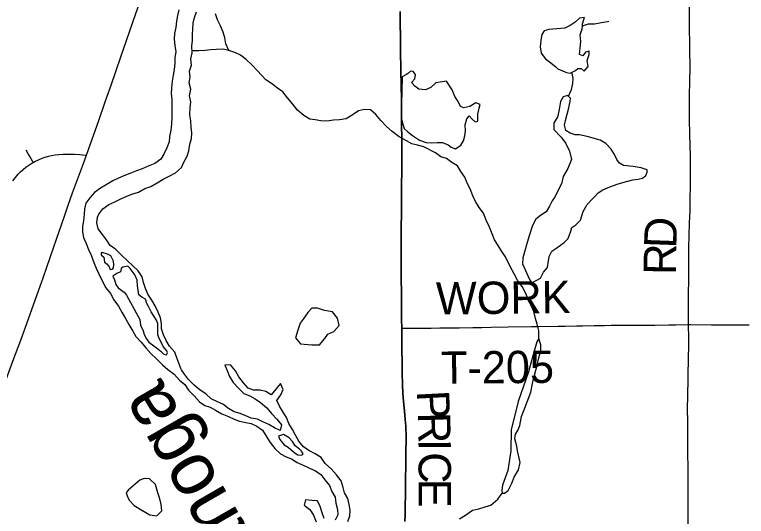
# Model space of a CAD drawing. Extents: x 0 to 34, y 0 to 22.
# Drawn here: x 4.358 to 5.643, y 18.429 to 19.311 of the extents above; entities that cross this region are included whole.
import ezdxf

# ---------------------------------------------------------------- set-up
doc = ezdxf.new("R2010")
doc.units = 0
for name, color, linetype in [('GM_X_City_Street', 7, 'Continuous'), ('GM_X_Corporation', 7, 'Continuous'), ('GM_X_County_Road', 7, 'Continuous'), ('GM_X_County_Road_Text', 7, 'Continuous'), ('GM_X_Major_River', 7, 'Continuous'), ('GM_X_Major_River_Text', 7, 'Continuous'), ('GM_X_Minor_Lake', 7, 'Continuous'), ('GM_X_Minor_River', 7, 'Continuous'), ('GM_X_Township_Road', 7, 'Continuous'), ('GM_X_Township_Road_Text', 7, 'Continuous')]:
    doc.layers.add(name, color=color, linetype=linetype)

msp = doc.modelspace()

# ---------------------------------------------------------------- linework, layer by layer
at = {"layer": 'GM_X_City_Street'}
for points in [[(4.3544, 19.0187), (4.3594, 19.0249), (4.3642, 19.0306), (4.3683, 19.0347), (4.3726, 19.0387), (4.3774, 19.0426), (4.3824, 19.0462), (4.3878, 19.0497), (4.3904, 19.051), (4.393, 19.0525), (4.3995, 19.0556), (4.4059, 19.0585), (4.4115, 19.0604), (4.417, 19.0621), (4.4225, 19.0633), (4.4291, 19.0645), (4.4355, 19.0652), (4.4432, 19.0658), (4.4525, 19.0658), (4.4626, 19.0657), (4.4723, 19.0651), (4.4818, 19.0641), (4.4839, 19.0639)], [(4.3904, 19.051), (4.3897, 19.0522), (4.3838, 19.0626), (4.381, 19.0674), (4.378, 19.0725)]]:
    msp.add_lwpolyline(points, dxfattribs=at)
at = {"layer": 'GM_X_Corporation'}
for points in [[(5.0433, 18.4204), (5.0435, 18.4306), (5.0437, 18.4402), (5.0439, 18.4515), (5.0441, 18.4627), (5.0443, 18.474), (5.0444, 18.4842), (5.0446, 18.4992), (5.0447, 18.5132), (5.0451, 18.5363), (5.0452, 18.5462), (5.0455, 18.5599), (5.0455, 18.5667), (5.0455, 18.5743), (5.0452, 18.582), (5.0449, 18.5875), (5.044, 18.5992), (5.0426, 18.6137), (5.0403, 18.6381), (5.0398, 18.6453), (5.0394, 18.6506), (5.0391, 18.6562), (5.0388, 18.6671), (5.0386, 18.6755), (5.0384, 18.6871), (5.0382, 18.7016), (5.0379, 18.721), (5.0377, 18.736), (5.0376, 18.7601), (5.0374, 18.7747), (5.0372, 18.7908), (5.0372, 18.8147), (5.0372, 18.8259), (5.037, 18.8431), (5.037, 18.8569), (5.0369, 18.8664), (5.0368, 18.8922), (5.0367, 18.9116), (5.0369, 18.9377), (5.0371, 18.9607), (5.0372, 18.9701), (5.0373, 18.9876), (5.0374, 19.0028), (5.0375, 19.0127), (5.0377, 19.0343), (5.038, 19.0561), (5.0379, 19.0696), (5.0378, 19.0934), (5.0375, 19.1174), (5.0374, 19.1254), (5.0373, 19.145), (5.0372, 19.1591), (5.0371, 19.1704), (5.037, 19.1778), (5.0367, 19.1888), (5.0362, 19.211), (5.036, 19.2246), (5.0358, 19.237), (5.0355, 19.2584), (5.0353, 19.2747), (5.035, 19.2928), (5.0349, 19.3162)], [(5.0433, 18.4204), (5.0435, 18.4306), (5.0437, 18.4402), (5.0439, 18.4515), (5.0441, 18.4627), (5.0443, 18.474), (5.0444, 18.4842), (5.0446, 18.4992), (5.0447, 18.5132), (5.0451, 18.5363), (5.0452, 18.5462), (5.0455, 18.5599), (5.0455, 18.5667), (5.0455, 18.5743), (5.0452, 18.582), (5.0449, 18.5875), (5.044, 18.5992), (5.0426, 18.6137), (5.0403, 18.6381), (5.0398, 18.6453), (5.0394, 18.6506), (5.0391, 18.6562), (5.0388, 18.6671), (5.0386, 18.6755), (5.0384, 18.6871), (5.0382, 18.7016), (5.0379, 18.721), (5.0377, 18.736), (5.0376, 18.7601), (5.0374, 18.7747), (5.0372, 18.7908), (5.0372, 18.8147), (5.0372, 18.8259), (5.037, 18.8431), (5.037, 18.8569), (5.0369, 18.8664), (5.0368, 18.8922), (5.0367, 18.9116), (5.0369, 18.9377), (5.0371, 18.9607), (5.0372, 18.9701), (5.0373, 18.9876), (5.0374, 19.0028), (5.0375, 19.0127), (5.0377, 19.0343), (5.038, 19.0561), (5.0379, 19.0696), (5.0378, 19.0934), (5.0375, 19.1174), (5.0374, 19.1254), (5.0373, 19.145), (5.0372, 19.1591), (5.0371, 19.1704), (5.037, 19.1778), (5.0367, 19.1888), (5.0362, 19.211), (5.036, 19.2246), (5.0358, 19.237), (5.0355, 19.2584), (5.0353, 19.2747), (5.035, 19.2928), (5.0349, 19.3162)], [(5.0349, 19.3162), (5.035, 19.2928), (5.0353, 19.2747), (5.0355, 19.2584), (5.0358, 19.237), (5.036, 19.2246), (5.0362, 19.211), (5.0367, 19.1888), (5.037, 19.1778), (5.0371, 19.1704), (5.0372, 19.1591), (5.0373, 19.145), (5.0374, 19.1254), (5.0375, 19.1174), (5.0378, 19.0934), (5.0379, 19.0696), (5.038, 19.0561), (5.0377, 19.0343), (5.0375, 19.0127), (5.0374, 19.0028), (5.0373, 18.9876), (5.0372, 18.9701), (5.0371, 18.9607), (5.0369, 18.9377), (5.0367, 18.9116), (5.0368, 18.8922), (5.0369, 18.8664), (5.037, 18.8569), (5.037, 18.8431), (5.0372, 18.8259), (5.0372, 18.8147), (5.0372, 18.7908), (5.0374, 18.7747), (5.0376, 18.7601), (5.0377, 18.736), (5.0379, 18.721), (5.0382, 18.7016), (5.0384, 18.6871), (5.0386, 18.6755), (5.0388, 18.6671), (5.0391, 18.6562), (5.0394, 18.6506), (5.0398, 18.6453), (5.0403, 18.6381), (5.0426, 18.6137), (5.044, 18.5992), (5.0449, 18.5875), (5.0452, 18.582), (5.0455, 18.5743), (5.0455, 18.5667), (5.0455, 18.5599), (5.0452, 18.5462), (5.0451, 18.5363), (5.0447, 18.5132), (5.0446, 18.4992), (5.0444, 18.4842), (5.0443, 18.474), (5.0441, 18.4627), (5.0439, 18.4515), (5.0437, 18.4402), (5.0435, 18.4306), (5.0433, 18.4204)]]:
    msp.add_lwpolyline(points, dxfattribs=at)
at = {"layer": 'GM_X_County_Road'}
for points in [[(4.4839, 19.0639), (4.4909, 19.0836), (4.5051, 19.1233), (4.5169, 19.1574), (4.527, 19.1868), (4.5441, 19.2367), (4.5702, 19.3113), (4.5896, 19.367), (4.6075, 19.4161), (4.6147, 19.4353), (4.6273, 19.4684), (4.6389, 19.498), (4.6405, 19.5022), (4.6422, 19.506), (4.6444, 19.5103), (4.6464, 19.5143), (4.6507, 19.5222), (4.6645, 19.5462), (4.6819, 19.5749), (4.704, 19.6102), (4.7229, 19.6416), (4.7349, 19.6613), (4.7525, 19.6876), (4.7582, 19.6961)], [(5.5416, 18.766), (5.5416, 18.7696), (5.5416, 18.7796), (5.5417, 18.8106), (5.542, 18.8535), (5.5419, 18.8777), (5.5419, 18.8882), (5.5422, 18.9006), (5.5427, 18.9225), (5.5435, 18.9448), (5.5442, 18.9652), (5.5443, 18.9701), (5.5445, 18.9794), (5.545, 19.0167), (5.5451, 19.0366), (5.5451, 19.0631), (5.5445, 19.0804), (5.5437, 19.1009), (5.5435, 19.1264), (5.5433, 19.1469), (5.5435, 19.1674), (5.544, 19.1947), (5.5443, 19.2171), (5.544, 19.2494), (5.5434, 19.2978), (5.5429, 19.3687)], [(4.3111, 18.581), (4.3127, 18.5856), (4.3213, 18.6094), (4.3384, 18.6567), (4.3547, 18.7017), (4.3685, 18.7389), (4.3821, 18.7762), (4.4003, 18.8271), (4.4077, 18.8483), (4.421, 18.8857), (4.4315, 18.9162), (4.4455, 18.9567), (4.4518, 18.9761), (4.4596, 18.9976), (4.4769, 19.0444), (4.4839, 19.0639)], [(5.5406, 18.402), (5.5406, 18.4299), (5.541, 18.4628), (5.5408, 18.4795), (5.5408, 18.5), (5.5408, 18.518), (5.5405, 18.5367), (5.5403, 18.5572), (5.5402, 18.5833), (5.54, 18.5988), (5.5398, 18.6144), (5.5402, 18.6442), (5.5405, 18.6504), (5.5408, 18.6616), (5.5411, 18.6845), (5.5412, 18.6982), (5.5419, 18.738), (5.5418, 18.7435), (5.5416, 18.7647), (5.5416, 18.766)]]:
    msp.add_lwpolyline(points, dxfattribs=at)
at = {"layer": 'GM_X_Major_River'}
for p, q in [((4.5142, 18.8844), (4.5154, 18.8757)), ((4.5576, 18.8112), (4.5779, 18.7749)), ((4.8313, 18.5546), (4.8381, 18.5505))]:
    msp.add_line(p, q, dxfattribs=at)
for points in [[(4.646, 19.3193), (4.6438, 19.3095), (4.642, 19.2992), (4.6406, 19.2882), (4.6387, 19.2776), (4.6381, 19.2677), (4.6393, 19.2567), (4.6409, 19.2457), (4.6394, 19.2358), (4.6391, 19.2256), (4.6381, 19.2142), (4.6363, 19.2047), (4.6345, 19.1941), (4.6334, 19.1823), (4.6327, 19.1721), (4.6336, 19.1618), (4.6338, 19.1307), (4.6335, 19.1182), (4.6321, 19.108), (4.6299, 19.0966), (4.6292, 19.0871), (4.6248, 19.0768), (4.6203, 19.0669), (4.6143, 19.057), (4.6038, 19.0493), (4.5925, 19.0447), (4.5819, 19.0401), (4.5717, 19.0362), (4.56, 19.0319), (4.5498, 19.0273), (4.54, 19.0234), (4.5302, 19.0188), (4.5186, 19.0119), (4.5084, 19.0057), (4.4982, 18.9984), (4.49, 18.9889), (4.4825, 18.9794), (4.4807, 18.9695), (4.4796, 18.96), (4.4789, 18.9482), (4.4771, 18.9383), (4.4768, 18.9289), (4.4788, 18.919), (4.4834, 18.9084), (4.4873, 18.8982), (4.4919, 18.888), (4.4969, 18.8752), (4.5008, 18.8653), (4.5054, 18.8555), (4.5112, 18.843), (4.5181, 18.8306), (4.5261, 18.8208), (4.5318, 18.8098), (4.5399, 18.7985), (4.5464, 18.7868), (4.5522, 18.777), (4.5583, 18.7664), (4.5656, 18.7547), (4.5709, 18.7449), (4.5801, 18.7351), (4.5881, 18.7253), (4.5969, 18.7155), (4.6072, 18.7057), (4.6175, 18.6952), (4.627, 18.6873), (4.6377, 18.679), (4.6472, 18.6685), (4.6567, 18.661), (4.6633, 18.6508), (4.6728, 18.641), (4.6823, 18.6304), (4.6919, 18.6237), (4.7013, 18.6207), (4.7108, 18.6159), (4.7219, 18.6091), (4.7336, 18.6047), (4.7435, 18.5998), (4.753, 18.5961), (4.7636, 18.5939), (4.7735, 18.5921), (4.783, 18.5872), (4.7929, 18.5805), (4.8005, 18.5684), (4.8067, 18.5586), (4.8147, 18.548), (4.825, 18.5386), (4.8348, 18.5338), (4.8443, 18.53), (4.8542, 18.5237), (4.8645, 18.5192), (4.8744, 18.514), (4.8861, 18.5091), (4.8956, 18.5028)], [(4.5031, 18.9548), (4.5057, 18.9601), (4.5128, 18.9697), (4.5233, 18.9774), (4.5339, 18.9817), (4.544, 18.9871), (4.5546, 18.9918), (4.5655, 18.9957), (4.5753, 18.9989), (4.5862, 19.0051), (4.5972, 19.009), (4.6081, 19.0152), (4.6186, 19.0214), (4.6292, 19.0272), (4.6405, 19.0331), (4.651, 19.0423), (4.655, 19.0518), (4.6606, 19.0622), (4.6635, 19.0717), (4.6653, 19.0831), (4.6686, 19.093), (4.6688, 19.1029), (4.668, 19.1128), (4.6671, 19.1234), (4.6655, 19.1351), (4.6661, 19.1473), (4.6671, 19.1576), (4.6651, 19.1682), (4.6672, 19.1796), (4.6644, 19.1913), (4.6662, 19.2012), (4.665, 19.2118), (4.6683, 19.2218), (4.667, 19.2335), (4.6695, 19.2438), (4.6687, 19.2552), (4.6701, 19.2655), (4.6699, 19.2757), (4.6706, 19.2852), (4.6716, 19.2962), (4.6738, 19.3061), (4.6771, 19.316)], [(4.6496, 18.6891), (4.6428, 18.7079), (4.6389, 18.7177), (4.6297, 18.7283), (4.624, 18.7381), (4.6194, 18.7483), (4.6159, 18.7585), (4.6158, 18.768), (4.6138, 18.7778), (4.6096, 18.7877), (4.6046, 18.799), (4.5985, 18.8088), (4.5916, 18.8198), (4.5877, 18.8296), (4.5842, 18.8398), (4.5815, 18.85), (4.575, 18.8606), (4.5654, 18.8696), (4.5555, 18.8787), (4.546, 18.8877), (4.5357, 18.8982), (4.5254, 18.905), (4.5193, 18.9148), (4.512, 18.9246), (4.5044, 18.9344), (4.502, 18.945), (4.5031, 18.9548)], [(4.5154, 18.8757), (4.52, 18.8723), (4.5235, 18.8678), (4.5258, 18.8629), (4.5295, 18.8633), (4.5314, 18.8656), (4.5321, 18.8713), (4.5313, 18.8773), (4.5267, 18.8868), (4.5206, 18.8898), (4.513, 18.8924), (4.51, 18.8919), (4.51, 18.8889), (4.5142, 18.8844)], [(4.5779, 18.7749), (4.5791, 18.765), (4.5837, 18.7548), (4.5853, 18.7484), (4.5891, 18.7412), (4.5934, 18.7352), (4.6021, 18.7288), (4.6093, 18.7236), (4.6151, 18.7187), (4.62, 18.7138), (4.6242, 18.7131), (4.6264, 18.7165), (4.6249, 18.7199), (4.6184, 18.7274), (4.6157, 18.7342), (4.6122, 18.7407), (4.6095, 18.7482), (4.6095, 18.7569), (4.609, 18.7679), (4.6067, 18.774), (4.6017, 18.7819), (4.5975, 18.7883), (4.5925, 18.7989), (4.5902, 18.8034), (4.5875, 18.8106), (4.581, 18.8144), (4.5757, 18.8185), (4.5737, 18.834), (4.5732, 18.8443), (4.5701, 18.8511), (4.5674, 18.8552), (4.5606, 18.8647), (4.5567, 18.8688), (4.5477, 18.8672), (4.545, 18.8645), (4.5436, 18.8585), (4.5372, 18.8561), (4.5304, 18.8511), (4.5331, 18.8447), (4.5354, 18.8364), (4.5396, 18.8304), (4.5499, 18.8229), (4.5541, 18.818), (4.5576, 18.8112)], [(4.9429, 18.42), (4.9466, 18.4299), (4.9472, 18.4398), (4.9452, 18.45), (4.9428, 18.4602), (4.9374, 18.4701), (4.935, 18.4799), (4.9315, 18.4913), (4.9234, 18.5022), (4.9142, 18.5119), (4.9035, 18.5217), (4.8962, 18.5326), (4.8859, 18.5386), (4.8745, 18.5449), (4.8649, 18.5512), (4.8569, 18.561), (4.8511, 18.5716), (4.8457, 18.5818), (4.8391, 18.5923), (4.8352, 18.6025), (4.8294, 18.6123), (4.8229, 18.6225), (4.8182, 18.6327), (4.8253, 18.6423), (4.8297, 18.6522), (4.8247, 18.6624), (4.8165, 18.6524), (4.8086, 18.6425), (4.7987, 18.6484), (4.7892, 18.6506), (4.7775, 18.6508), (4.768, 18.6541), (4.7599, 18.6639), (4.7518, 18.6745), (4.7457, 18.6846), (4.7368, 18.6952), (4.727, 18.695), (4.7313, 18.6852), (4.7352, 18.6746), (4.7414, 18.6641), (4.7509, 18.6543), (4.7605, 18.6449), (4.7708, 18.6409), (4.7803, 18.6353), (4.7898, 18.6293), (4.8006, 18.6196), (4.809, 18.6098), (4.8182, 18.6), (4.8263, 18.5899), (4.8241, 18.58), (4.8142, 18.5844), (4.8043, 18.5904), (4.7936, 18.5952), (4.7841, 18.5996), (4.7735, 18.6014), (4.7636, 18.6055), (4.7541, 18.6095), (4.7435, 18.6125), (4.7332, 18.6184), (4.7236, 18.6259), (4.7141, 18.6303), (4.7031, 18.6355), (4.6935, 18.6441), (4.6839, 18.6505), (4.6732, 18.6595), (4.6633, 18.6696), (4.6561, 18.6789), (4.651, 18.6866), (4.6496, 18.6891)], [(4.8381, 18.5505), (4.8431, 18.5467), (4.8465, 18.5433), (4.8503, 18.54), (4.8553, 18.5373), (4.8621, 18.5363), (4.8643, 18.5389), (4.8616, 18.5438), (4.8582, 18.5468), (4.8506, 18.5532), (4.846, 18.5604), (4.8399, 18.5668), (4.83, 18.5728), (4.8213, 18.5701), (4.8236, 18.564), (4.8313, 18.5546)], [(4.8956, 18.5028), (4.9029, 18.493), (4.9106, 18.4831), (4.9152, 18.4729), (4.9206, 18.4624), (4.9221, 18.4521), (4.9249, 18.4412), (4.9253, 18.4317), (4.9209, 18.4222)], [(4.9012, 18.4254), (4.8977, 18.4353), (4.8946, 18.4462), (4.8899, 18.4564), (4.8797, 18.4567), (4.8687, 18.4582), (4.8665, 18.4487), (4.8764, 18.4408), (4.883, 18.431), (4.8872, 18.4192)]]:
    msp.add_lwpolyline(points, dxfattribs=at)
at = {"layer": 'GM_X_Minor_Lake'}
for p, q in [((5.3244, 19.287), (5.2961, 19.2849)), ((5.0382, 19.2014), (5.0365, 19.1293)), ((5.3182, 19.0137), (5.3059, 18.9892)), ((4.873, 18.7874), (4.8644, 18.7756)), ((5.2602, 18.6831), (5.2425, 18.631)), ((4.5774, 18.4923), (4.5571, 18.4747))]:
    msp.add_line(p, q, dxfattribs=at)
for points in [[(5.2961, 19.2849), (5.2881, 19.2822), (5.2837, 19.2757), (5.2822, 19.2659), (5.2808, 19.2541), (5.2828, 19.2431), (5.2904, 19.2333), (5.2973, 19.2277), (5.3083, 19.2194), (5.3121, 19.2156), (5.3201, 19.2119), (5.3269, 19.2093), (5.3338, 19.2082), (5.3432, 19.2125), (5.3473, 19.2163), (5.353, 19.216), (5.3583, 19.2118), (5.3651, 19.2195), (5.3635, 19.2305), (5.3668, 19.2411), (5.3668, 19.2464), (5.3603, 19.2448), (5.3558, 19.2387), (5.3502, 19.241), (5.3512, 19.2524), (5.3523, 19.2634), (5.3514, 19.2755), (5.3547, 19.2861), (5.3551, 19.2903), (5.355, 19.2949), (5.3587, 19.3059), (5.35, 19.3047), (5.3425, 19.2978), (5.3335, 19.2917), (5.3244, 19.287)], [(5.0365, 19.1293), (5.0396, 19.1183), (5.042, 19.1108), (5.0484, 19.1048), (5.0568, 19.0984), (5.069, 19.0901), (5.0804, 19.0864), (5.0906, 19.0854), (5.1, 19.0862), (5.1095, 19.0859), (5.1194, 19.0818), (5.1247, 19.0777), (5.1323, 19.0751), (5.1413, 19.0816), (5.1462, 19.0892), (5.1484, 19.0976), (5.1498, 19.1067), (5.1494, 19.1173), (5.152, 19.1279), (5.1561, 19.1333), (5.161, 19.128), (5.1668, 19.1224), (5.1713, 19.1239), (5.1716, 19.1357), (5.1738, 19.1467), (5.1756, 19.1531), (5.1676, 19.1561), (5.1575, 19.1492), (5.1469, 19.1469), (5.1408, 19.1495), (5.137, 19.1582), (5.1312, 19.1672), (5.1262, 19.1789), (5.1166, 19.1937), (5.0977, 19.1909), (5.0891, 19.1828), (5.0797, 19.1786), (5.0675, 19.18), (5.0607, 19.1849), (5.0561, 19.1902), (5.0557, 19.1924), (5.0606, 19.1982), (5.0617, 19.2054), (5.0575, 19.211), (5.0533, 19.2114), (5.0495, 19.2083), (5.0458, 19.2056), (5.0382, 19.2014)], [(5.3059, 18.9892), (5.3022, 18.9838), (5.297, 18.9743), (5.2914, 18.9644), (5.2812, 18.9579), (5.2733, 18.9513), (5.2677, 18.9403), (5.2618, 18.9221), (5.257, 18.9061), (5.254, 18.8958), (5.2503, 18.8833), (5.2497, 18.8727), (5.2551, 18.8613), (5.262, 18.8454), (5.2662, 18.8394), (5.2813, 18.8475), (5.2869, 18.8581), (5.294, 18.8665), (5.2958, 18.8783), (5.2965, 18.8859), (5.3014, 18.895), (5.3104, 18.9012), (5.3232, 18.9104), (5.3299, 18.9176), (5.334, 18.9287), (5.3366, 18.937), (5.3434, 18.9413), (5.352, 18.9497), (5.3564, 18.9649), (5.3632, 18.9771), (5.3729, 18.9874), (5.3767, 18.9912), (5.3827, 18.9977), (5.391, 19.0031), (5.4034, 19.0081), (5.4181, 19.0132), (5.4325, 19.0174), (5.4438, 19.0206), (5.4529, 19.0214), (5.4605, 19.0233), (5.4665, 19.0283), (5.4691, 19.034), (5.4687, 19.0382), (5.4584, 19.0415), (5.4444, 19.0437), (5.4274, 19.0458), (5.4205, 19.0496), (5.4155, 19.056), (5.4113, 19.0651), (5.4056, 19.0745), (5.3964, 19.0843), (5.3861, 19.0903), (5.3634, 19.0969), (5.3497, 19.0995), (5.3422, 19.0994), (5.3334, 19.1024), (5.3258, 19.1073), (5.3239, 19.1164), (5.3253, 19.1251), (5.3286, 19.1357), (5.3308, 19.1445), (5.3338, 19.1585), (5.3341, 19.1638), (5.3291, 19.1687), (5.3212, 19.1664), (5.3167, 19.1584), (5.3142, 19.144), (5.3113, 19.1307), (5.3049, 19.1208), (5.3046, 19.109), (5.3176, 19.0954), (5.326, 19.0841), (5.3322, 19.0709), (5.3357, 19.0561), (5.3294, 19.0405), (5.3212, 19.0264), (5.3182, 19.0137)], [(4.8644, 18.7756), (4.8595, 18.7684), (4.8551, 18.7562), (4.851, 18.7425), (4.8598, 18.732), (4.8795, 18.7302), (4.8935, 18.7303), (4.9029, 18.7414), (4.9081, 18.749), (4.9183, 18.754), (4.9277, 18.7647), (4.9249, 18.7772), (4.9161, 18.7885), (4.9021, 18.7907), (4.8896, 18.7948), (4.8798, 18.7951), (4.873, 18.7874)], [(5.2425, 18.631), (5.23, 18.5808), (5.2295, 18.5444), (5.2241, 18.5095), (5.2145, 18.4836), (5.2134, 18.4752), (5.2142, 18.4699), (5.218, 18.47), (5.2247, 18.4746), (5.2311, 18.4871), (5.2352, 18.4978), (5.2426, 18.5107), (5.2456, 18.5237), (5.2412, 18.5441), (5.24, 18.5524), (5.2381, 18.5585), (5.2365, 18.5653), (5.2376, 18.5733), (5.2417, 18.5801), (5.2454, 18.5889), (5.2483, 18.6045), (5.2532, 18.6178), (5.258, 18.6303), (5.2643, 18.6471), (5.2676, 18.6627), (5.2709, 18.6771), (5.2756, 18.695), (5.2786, 18.7079), (5.2823, 18.7204), (5.2822, 18.7307), (5.2787, 18.7416), (5.2753, 18.7355), (5.2702, 18.7196), (5.2654, 18.7021), (5.2602, 18.6831)], [(4.5571, 18.4747), (4.5538, 18.4705), (4.5553, 18.4648), (4.5592, 18.4573), (4.5676, 18.4482), (4.5809, 18.44), (4.5953, 18.4314), (4.6078, 18.43), (4.6161, 18.4384), (4.6149, 18.4498), (4.6129, 18.4596), (4.609, 18.4702), (4.6051, 18.4849), (4.5945, 18.4951), (4.5854, 18.4954), (4.5774, 18.4923)]]:
    msp.add_lwpolyline(points, dxfattribs=at)
at = {"layer": 'GM_X_Minor_River'}
for points in [[(4.734, 19.2476), (4.729, 19.2597), (4.727, 19.2699), (4.7243, 19.2801), (4.7192, 19.2911), (4.7139, 19.302), (4.7104, 19.3123)], [(5.3551, 19.2915), (5.366, 19.2946), (5.3766, 19.2947), (5.3887, 19.297), (5.3989, 19.299), (5.4016, 19.2994)], [(5.2787, 18.7416), (5.2786, 18.7549), (5.2758, 18.7666), (5.2727, 18.7765), (5.2696, 18.789), (5.2642, 18.8007), (5.2596, 18.8109), (5.2554, 18.8219), (5.2492, 18.8332), (5.2416, 18.843), (5.235, 18.8555), (5.2289, 18.8668), (5.2201, 18.8849), (5.2136, 18.8948), (5.207, 18.9053), (5.2005, 18.9151), (5.1967, 18.9257), (5.1917, 18.9371), (5.1863, 18.9495), (5.1816, 18.962), (5.174, 18.9718), (5.1675, 18.9824), (5.1628, 18.9922), (5.1582, 19.0047), (5.1528, 19.0149), (5.1486, 19.0251), (5.1417, 19.0349), (5.1356, 19.0451), (5.1257, 19.0507), (5.1162, 19.0582), (5.1063, 19.0612), (5.0968, 19.068), (5.0763, 19.0784), (5.0656, 19.0814), (5.0554, 19.0839), (5.0459, 19.0888), (5.0334, 19.0963), (5.0208, 19.1053), (5.0109, 19.1143), (5.001, 19.1249), (4.9922, 19.1354), (4.9827, 19.1433), (4.9721, 19.1444), (4.9615, 19.142), (4.9506, 19.1343), (4.94, 19.1278), (4.9283, 19.1258), (4.9177, 19.1254), (4.9064, 19.1238), (4.8958, 19.1241), (4.8859, 19.1259), (4.8761, 19.1269), (4.8658, 19.1337), (4.8544, 19.1427), (4.8467, 19.1533), (4.8372, 19.1646), (4.8291, 19.1751), (4.8196, 19.1815), (4.809, 19.1898), (4.7987, 19.1965), (4.7846, 19.2119), (4.7743, 19.2225), (4.7644, 19.2319), (4.7545, 19.2398), (4.7446, 19.2446), (4.734, 19.2476), (4.7241, 19.2502), (4.7124, 19.2497), (4.7025, 19.2492), (4.6916, 19.2476), (4.6814, 19.2472), (4.6715, 19.2475), (4.6692, 19.2477)], [(5.3304, 19.1675), (5.3362, 19.1794), (5.3384, 19.1901), (5.3387, 19.1995), (5.3366, 19.2095)], [(5.1392, 18.4246), (5.1498, 18.4311), (5.1622, 18.4396), (5.1731, 18.4423), (5.1841, 18.4454), (5.1943, 18.4489), (5.2063, 18.4593), (5.2142, 18.4699)]]:
    msp.add_lwpolyline(points, dxfattribs=at)
at = {"layer": 'GM_X_Township_Road'}
for points in [[(5.0378, 18.7596), (5.0376, 18.7741), (5.0374, 18.7902), (5.0374, 18.8141), (5.0374, 18.8253), (5.0372, 18.8426), (5.0372, 18.8564), (5.0371, 18.8659), (5.037, 18.8916), (5.0369, 18.911), (5.0371, 18.9371), (5.0373, 18.9602), (5.0374, 18.9695), (5.0375, 18.987), (5.0376, 19.0023), (5.0377, 19.0121), (5.0379, 19.0338), (5.0382, 19.0556), (5.0381, 19.0691), (5.038, 19.0929), (5.0377, 19.1169), (5.0376, 19.1249), (5.0375, 19.1444), (5.0374, 19.1585), (5.0373, 19.1698), (5.0372, 19.1772), (5.0369, 19.1883), (5.0364, 19.2105), (5.0362, 19.2241), (5.036, 19.2365), (5.0357, 19.2579), (5.0355, 19.2742), (5.0352, 19.2922), (5.0351, 19.3156)], [(5.0378, 18.7596), (5.0665, 18.7598), (5.0895, 18.7599), (5.1044, 18.7601), (5.1385, 18.7606), (5.1628, 18.761), (5.1783, 18.7612), (5.195, 18.7618), (5.2249, 18.7619), (5.2659, 18.7624), (5.2783, 18.7625), (5.3124, 18.7632), (5.3249, 18.7634), (5.3447, 18.7638), (5.3552, 18.7641), (5.3757, 18.7642), (5.3937, 18.7646), (5.4055, 18.7649), (5.426, 18.7649), (5.444, 18.765), (5.4826, 18.7652), (5.5068, 18.7654), (5.5192, 18.7656), (5.5416, 18.766)], [(5.0435, 18.4198), (5.0437, 18.4301), (5.0439, 18.4396), (5.0441, 18.451), (5.0443, 18.4622), (5.0445, 18.4734), (5.0446, 18.4837), (5.0448, 18.4987), (5.0449, 18.5127), (5.0453, 18.5357), (5.0455, 18.5456), (5.0457, 18.5593), (5.0457, 18.5662), (5.0457, 18.5738), (5.0454, 18.5815), (5.0451, 18.587), (5.0442, 18.5986), (5.0428, 18.6132), (5.0405, 18.6376), (5.04, 18.6448), (5.0396, 18.65), (5.0393, 18.6557), (5.039, 18.6666), (5.0388, 18.675), (5.0386, 18.6865), (5.0384, 18.7011), (5.0381, 18.7205), (5.0379, 18.7355), (5.0378, 18.7596)], [(5.5416, 18.766), (5.5451, 18.766), (5.5817, 18.7658), (5.6078, 18.7658), (5.6189, 18.7658), (5.6481, 18.7658)]]:
    msp.add_lwpolyline(points, dxfattribs=at)

# ---------------------------------------------------------------- texts
at = {"layer": 'GM_X_County_Road_Text'}
for s, rotation, p in [('D', 87.8976, (5.5199, 18.8995)), ('R', 89.2467, (5.5193, 18.8532))]:
    msp.add_text(s, height=0.0568, rotation=rotation, dxfattribs=at).set_placement(p)
at = {"layer": 'GM_X_Major_River_Text'}
msp.add_text('Cuyahoga', height=0.09474, rotation=119.9689, dxfattribs=at).set_placement((4.9026, 18.1729))
at = {"layer": 'GM_X_Township_Road_Text'}
for s, height, rotation, p in [('WORK', 0.05682, 0.6735, (5.0981, 18.7836)), ('T-205', 0.05682, 0.5557, (5.1069, 18.6618)), ('P', 0.0568, 272.9663, (5.0639, 18.6492)), ('R', 0.0568, 271.5457, (5.0659, 18.6113)), ('I', 0.0568, 270.3279, (5.0671, 18.5649)), ('C', 0.0568, 270.0156, (5.0673, 18.5417)), ('E', 0.0568, 270, (5.0673, 18.495))]:
    msp.add_text(s, height=height, rotation=rotation, dxfattribs=at).set_placement(p)

doc.saveas('drawing.dxf')
